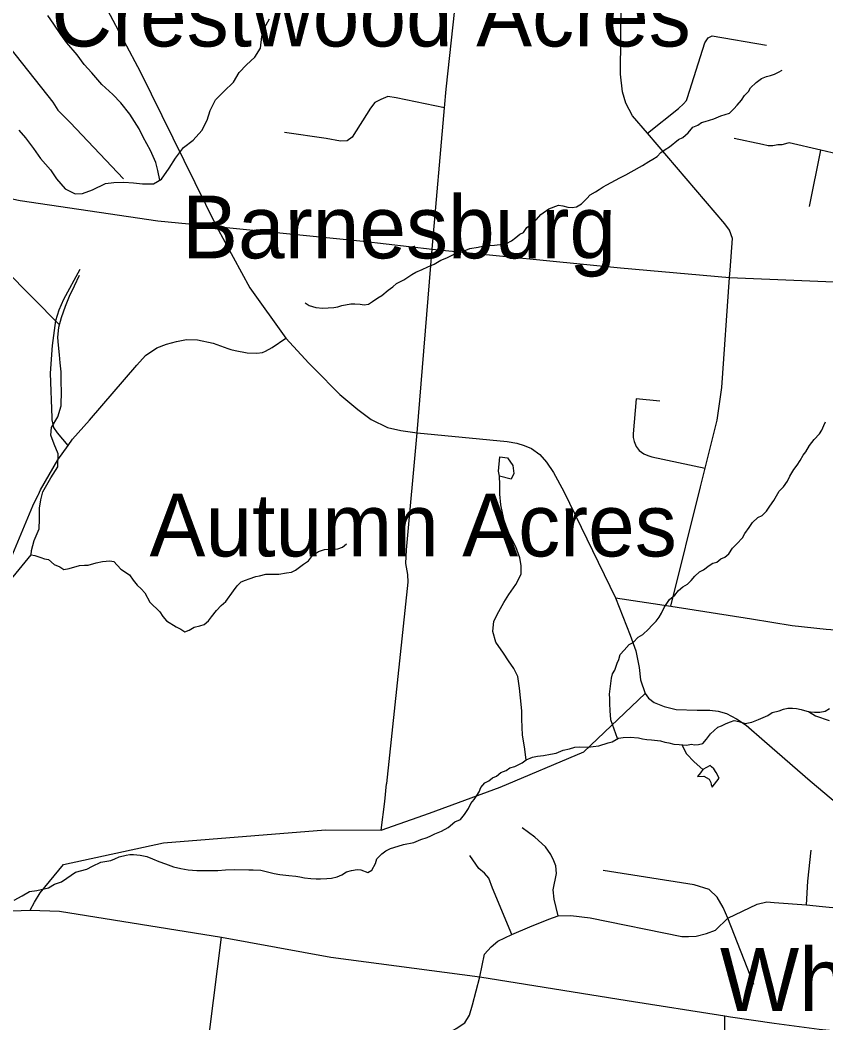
# Model space of a CAD drawing. Extents: x 0 to 34, y 0 to 22.
# Drawn here: x 2.395 to 3.408, y 15.023 to 16.285 of the extents above; entities that cross this region are included whole.
import ezdxf

# ---------------------------------------------------------------- set-up
doc = ezdxf.new("R2010")
doc.units = 0
for name, color, linetype in [('GM_X_County_Road', 7, 'Continuous'), ('GM_X_County_ROW', 7, 'Continuous'), ('GM_X_Minor_Lake', 7, 'Continuous'), ('GM_X_Minor_River', 7, 'Continuous'), ('GM_X_Township_Subdivision', 7, 'Continuous'), ('GM_X_Unincorporated_Text', 7, 'Continuous')]:
    doc.layers.add(name, color=color, linetype=linetype)

msp = doc.modelspace()

# ---------------------------------------------------------------- linework, layer by layer
at = {"layer": 'GM_X_County_Road'}
for points in [[(2.8559, 15.3242), (2.8828, 15.5776), (2.8823, 15.5871), (2.88, 15.6009), (2.8808, 15.6183), (2.8941, 15.7652), (2.913, 15.9963), (2.9286, 16.1743), (2.9306, 16.1979), (2.9499, 16.3756), (2.9714, 16.57), (2.9729, 16.5972), (2.9738, 16.6003), (2.9747, 16.6018), (2.978, 16.6059), (2.9836, 16.6083), (3.0077, 16.6072)], [(3.2878, 15.9702), (3.2906, 16.01), (3.287, 16.0204), (3.2811, 16.0285), (3.1838, 16.1424), (3.1651, 16.1641), (3.1565, 16.1802), (3.1523, 16.1945), (3.1498, 16.2167), (3.1509, 16.3102), (3.153, 16.3194), (3.1554, 16.3229), (3.1594, 16.3234), (3.1901, 16.3171), (3.1974, 16.3189), (3.2011, 16.3245), (3.2039, 16.3381), (3.2263, 16.5685)], [(2.2074, 16.5345), (2.2273, 16.5312), (2.2755, 16.511), (2.3238, 16.4892), (2.3831, 16.4487), (2.4345, 16.4035), (2.4589, 16.3735), (2.484, 16.336), (2.5458, 16.2199), (2.6419, 16.0249), (2.6836, 15.948), (2.7291, 15.8843), (2.758, 15.8531), (2.7648, 15.8462)], [(2.208, 16.349), (2.2477, 16.3455), (2.274, 16.3389), (2.2886, 16.332), (2.3179, 16.3136), (2.3818, 16.2496), (2.4358, 16.1813), (2.4424, 16.1714), (2.4579, 16.1557), (2.5248, 16.0849)], [(2.0624, 16.1544), (2.0789, 16.1495), (2.3218, 16.0727), (2.3948, 16.0576), (2.5679, 16.0322), (2.6419, 16.0249), (2.8264, 16.0064), (2.913, 15.9963), (3.15, 15.9729), (3.2871, 15.9607), (3.469, 15.9531), (3.6377, 15.9467), (3.7269, 15.9403), (3.8777, 15.9247), (3.9714, 15.9095), (4.1621, 15.8689), (4.3548, 15.8285)], [(2.4351, 15.7841), (2.4329, 15.8403), (2.4357, 15.8752), (2.4399, 15.9066), (2.444, 15.9202), (2.4497, 15.9337), (2.4704, 15.9712)], [(3.2132, 15.5475), (3.2504, 15.6976), (3.2563, 15.7208), (3.2715, 15.7814), (3.2775, 15.8223), (3.2871, 15.9607), (3.2878, 15.9702), (3.2878, 15.9702)], [(2.4175, 15.6875), (2.4178, 15.6879), (2.4205, 15.6936), (2.4423, 15.7314), (2.4552, 15.7496), (2.4608, 15.7576), (2.4819, 15.7813), (2.5417, 15.8505), (2.5526, 15.8628), (2.5669, 15.8723), (2.5788, 15.8769), (2.5914, 15.8804), (2.604, 15.8828), (2.618, 15.8824), (2.6376, 15.8781), (2.6561, 15.8713), (2.6599, 15.8703), (2.6655, 15.8691), (2.6802, 15.8661), (2.6925, 15.8656), (2.6998, 15.8665), (2.7035, 15.868), (2.7119, 15.8726), (2.7291, 15.8843)], [(2.7648, 15.8462), (2.7968, 15.8135), (2.8196, 15.7946), (2.8362, 15.7823), (2.8568, 15.7721), (2.8737, 15.7683), (2.8941, 15.7652), (3.0075, 15.7545), (3.0197, 15.7525), (3.0289, 15.7494), (3.0381, 15.7458), (3.0483, 15.7382), (3.057, 15.7285), (3.0657, 15.7154), (3.0785, 15.6914), (3.1437, 15.5578), (3.162, 15.5109), (3.1691, 15.491), (3.1734, 15.4703), (3.1752, 15.4547), (3.1808, 15.4374), (3.185, 15.4317), (3.1922, 15.4263), (3.2048, 15.421), (3.2199, 15.4175), (3.2464, 15.4165), (3.2622, 15.4165), (3.2728, 15.4154), (3.2832, 15.4124), (3.2958, 15.4054), (3.3078, 15.3978), (3.331, 15.3776), (3.3884, 15.3276), (3.4866, 15.245)], [(2.4552, 15.7496), (2.4417, 15.7656), (2.4373, 15.7722), (2.4352, 15.7818), (2.4352, 15.7838), (2.4351, 15.7841)], [(2.2258, 15.2235), (2.2523, 15.2469), (2.2626, 15.258), (2.2702, 15.2722), (2.2781, 15.2876), (2.2823, 15.3117), (2.2837, 15.3313), (2.289, 15.3499), (2.3002, 15.3794), (2.3158, 15.4331), (2.3396, 15.5024), (2.3499, 15.5283), (2.3567, 15.552), (2.3636, 15.5654), (2.3774, 15.5931), (2.4109, 15.6737), (2.4175, 15.6875)], [(3.1437, 15.5578), (3.2132, 15.5475), (3.3147, 15.5315), (3.3657, 15.5231), (3.4084, 15.5185), (3.4388, 15.5162), (3.6274, 15.5008)], [(2.2258, 15.2235), (2.2987, 15.186), (2.3184, 15.1766), (2.3423, 15.1693), (2.373, 15.1638), (2.4076, 15.1648), (2.4442, 15.1636), (2.6483, 15.131), (2.7856, 15.1056), (2.9731, 15.0809), (3.1585, 15.0511), (3.281, 15.0319), (3.2884, 15.0308), (3.343, 15.0226), (3.3998, 15.0151), (3.5922, 14.9963), (3.5999, 14.9956)], [(2.4076, 15.1648), (2.4128, 15.1748), (2.4199, 15.1866), (2.4496, 15.2222)], [(2.6198, 14.8825), (2.6281, 14.9717), (2.6483, 15.131)]]:
    msp.add_lwpolyline(points, dxfattribs=at)
at = {"layer": 'GM_X_County_ROW'}
for points in [[(2.4496, 15.2222), (2.5753, 15.2496), (2.6899, 15.2589), (2.7788, 15.2659), (2.8491, 15.2655), (2.9098, 15.287), (2.9987, 15.3197), (3.104, 15.3642), (3.1808, 15.4374)], [(2.8491, 15.2655), (2.8535, 15.3015), (2.8558, 15.3238), (2.8559, 15.3242)]]:
    msp.add_lwpolyline(points, dxfattribs=at)
at = {"layer": 'GM_X_Minor_Lake'}
for points in [[(2.9979, 15.7108), (2.9965, 15.7173), (2.998, 15.7352), (3.0079, 15.7338), (3.0145, 15.7242), (3.0158, 15.7143), (3.0126, 15.7071)], [(3.0126, 15.7071), (2.9979, 15.7108)], [(3.2534, 15.3417), (3.2505, 15.3376), (3.2466, 15.3331), (3.2546, 15.3333), (3.2613, 15.3297), (3.2635, 15.3255), (3.2638, 15.3228), (3.2653, 15.3198), (3.2739, 15.331), (3.2702, 15.3379), (3.2673, 15.3425), (3.2643, 15.3452), (3.2628, 15.3468)], [(3.2628, 15.3468), (3.2534, 15.3417)]]:
    msp.add_lwpolyline(points, dxfattribs=at)
at = {"layer": 'GM_X_Minor_River'}
msp.add_line((2.3754, 15.9707), (2.4443, 15.9014), dxfattribs=at)
for points in [[(2.5705, 16.0832), (2.568, 16.0956), (2.5656, 16.1055), (2.5587, 16.1205), (2.5496, 16.1375), (2.5446, 16.1479), (2.5328, 16.1664), (2.5214, 16.1804), (2.5114, 16.1909), (2.4977, 16.2038), (2.4851, 16.2182), (2.4755, 16.2287), (2.4666, 16.241), (2.4537, 16.2562), (2.446, 16.2667), (2.4372, 16.2794), (2.4295, 16.2903)], [(2.3933, 16.1462), (2.4018, 16.1365), (2.4117, 16.123), (2.4205, 16.1106), (2.4331, 16.0962), (2.4404, 16.085), (2.4515, 16.0722), (2.4639, 16.0662), (2.4734, 16.0667), (2.4857, 16.0713), (2.5022, 16.0789), (2.5125, 16.0802), (2.5251, 16.0806), (2.5376, 16.08), (2.5489, 16.0785), (2.5626, 16.0786), (2.5727, 16.0844), (2.5821, 16.0983), (2.5904, 16.111), (2.6002, 16.1244), (2.6126, 16.1337), (2.6232, 16.1456), (2.6299, 16.1587), (2.634, 16.1708), (2.6404, 16.1843), (2.651, 16.1947), (2.663, 16.2066), (2.6705, 16.2186), (2.6795, 16.2282), (2.69, 16.2379), (2.6971, 16.2495), (2.699, 16.2639), (2.7023, 16.2748), (2.7083, 16.2861)], [(2.7533, 15.929), (2.7582, 15.9258), (2.7668, 15.9229), (2.7756, 15.9223), (2.7824, 15.9225), (2.7893, 15.9231), (2.7946, 15.9241), (2.7996, 15.9255), (2.8107, 15.9278), (2.816, 15.9277), (2.8225, 15.9271), (2.8274, 15.9266), (2.8331, 15.9272), (2.8382, 15.9305), (2.8447, 15.9352), (2.8498, 15.9381), (2.8579, 15.9451), (2.8638, 15.9492), (2.8684, 15.9532), (2.8773, 15.9579), (2.8874, 15.9645), (2.8924, 15.9674), (2.9005, 15.971), (2.9078, 15.9742), (2.9155, 15.9774), (2.924, 15.9825), (2.9317, 15.9857), (2.9398, 15.9897), (2.9482, 15.9921), (2.9605, 15.9975), (2.9708, 15.9991), (2.98, 16.0011), (2.9914, 16.0016), (3.0021, 16.0028), (3.0067, 16.0038), (3.0129, 16.0071), (3.0183, 16.0111), (3.0234, 16.0152), (3.028, 16.0173), (3.032, 16.0237), (3.0413, 16.0303), (3.0499, 16.0399), (3.06, 16.0473), (3.0719, 16.0519), (3.0776, 16.051), (3.0836, 16.0493), (3.0893, 16.0487), (3.0947, 16.0497), (3.1008, 16.0534), (3.1075, 16.0604), (3.1118, 16.0649), (3.1184, 16.0685), (3.123, 16.0714), (3.128, 16.0751), (3.1327, 16.0776), (3.1489, 16.0863), (3.1566, 16.0899), (3.1635, 16.0939), (3.1778, 16.1019), (3.1856, 16.1066), (3.1906, 16.1099), (3.196, 16.1132), (3.2007, 16.118), (3.2061, 16.122), (3.2116, 16.1253), (3.2228, 16.1345), (3.2282, 16.137), (3.2349, 16.1429), (3.2411, 16.15), (3.2473, 16.1525), (3.2519, 16.1558), (3.2565, 16.1572), (3.2673, 16.1603), (3.2761, 16.1642), (3.2815, 16.166), (3.2869, 16.1677), (3.2923, 16.1729), (3.2966, 16.1777), (3.3021, 16.1841), (3.3061, 16.1897), (3.3108, 16.1949), (3.3136, 16.1994), (3.3206, 16.206), (3.3272, 16.2112), (3.3337, 16.2136), (3.3387, 16.215), (3.3437, 16.2168), (3.3487, 16.2193), (3.3534, 16.2215)], [(2.4089, 15.6119), (2.4093, 15.6172), (2.4126, 15.63), (2.4187, 15.6447), (2.4194, 15.6569), (2.4193, 15.6706), (2.4207, 15.6812), (2.4236, 15.691), (2.4335, 15.7086), (2.4422, 15.7225), (2.4426, 15.7388), (2.4376, 15.7511), (2.4333, 15.7623), (2.4343, 15.7721), (2.4422, 15.7856), (2.4464, 15.7992), (2.4468, 15.8182), (2.4463, 15.8285), (2.4463, 15.8422), (2.4454, 15.8536), (2.4445, 15.8635), (2.4429, 15.8757), (2.4424, 15.8853), (2.4435, 15.8985), (2.4468, 15.9103), (2.4517, 15.9246), (2.457, 15.9374), (2.4634, 15.9505), (2.4694, 15.9637)], [(3.1463, 15.3807), (3.1376, 15.4042), (3.1374, 15.4107), (3.1371, 15.4152), (3.1367, 15.4252), (3.1364, 15.4313), (3.1362, 15.4366), (3.1368, 15.4434), (3.1377, 15.4499), (3.1387, 15.4567), (3.1399, 15.4624), (3.1427, 15.4669), (3.1456, 15.4756), (3.1477, 15.4801), (3.1497, 15.4865), (3.1544, 15.4921), (3.1607, 15.4991), (3.1657, 15.5017), (3.172, 15.5083), (3.1782, 15.5116), (3.1852, 15.5186), (3.1895, 15.5231), (3.1946, 15.5283), (3.1985, 15.5335), (3.2013, 15.5384), (3.2049, 15.5455), (3.2117, 15.5556), (3.2183, 15.5611), (3.223, 15.5671), (3.2285, 15.5715), (3.2343, 15.5748), (3.239, 15.5796), (3.2433, 15.5852), (3.2491, 15.5907), (3.2542, 15.5932), (3.2615, 15.5984), (3.2662, 15.6013), (3.2711, 15.6027), (3.2762, 15.6067), (3.2812, 15.6089), (3.2863, 15.6133), (3.2906, 15.6204), (3.2961, 15.6256), (3.3032, 15.6334), (3.3063, 15.6386), (3.3119, 15.6465), (3.3159, 15.6524), (3.3225, 15.6587), (3.3283, 15.6616), (3.3337, 15.6668), (3.3377, 15.6732), (3.3428, 15.6803), (3.3496, 15.6919), (3.3551, 15.6974), (3.3599, 15.7045), (3.3631, 15.7109), (3.3679, 15.7192), (3.3722, 15.7247), (3.3758, 15.7304), (3.3798, 15.7371), (3.3829, 15.7416), (3.3877, 15.7495), (3.3936, 15.7569), (3.4003, 15.7643), (3.4031, 15.7688), (3.4055, 15.7745), (3.4079, 15.7794)], [(3.0313, 15.3539), (3.0291, 15.3704), (3.0268, 15.3849), (3.0263, 15.3952), (3.0258, 15.4051), (3.0257, 15.4158), (3.0242, 15.4322), (3.0229, 15.444), (3.021, 15.4589), (3.0156, 15.4689), (3.009, 15.4785), (3.0027, 15.4882), (2.9932, 15.5021), (2.9893, 15.5155), (2.9908, 15.5284), (2.9968, 15.5408), (3.0031, 15.5521), (3.0095, 15.5618), (3.0185, 15.5745), (3.0249, 15.5877), (3.0252, 15.5987), (3.0235, 15.6083), (3.0182, 15.6221), (3.0091, 15.6394), (3.0038, 15.6551), (3.0017, 15.6647), (2.9993, 15.6747), (2.9981, 15.6884), (2.998, 15.7005), (2.9979, 15.7108)], [(2.4089, 15.6119), (2.4134, 15.611), (2.421, 15.6085), (2.4255, 15.6069), (2.4304, 15.606), (2.4375, 15.5997), (2.4446, 15.5968), (2.4499, 15.5936), (2.4567, 15.5946), (2.4694, 15.5984), (2.4759, 15.599), (2.4804, 15.5989), (2.4904, 15.602), (2.4984, 15.6037), (2.5076, 15.6042), (2.5129, 15.6037), (2.5214, 15.5939), (2.5322, 15.5868), (2.537, 15.5802), (2.5421, 15.5739), (2.5469, 15.5692), (2.5517, 15.5641), (2.5579, 15.5525), (2.5705, 15.5404), (2.5745, 15.5342), (2.5789, 15.5287), (2.5913, 15.5215), (2.5969, 15.5183), (2.6021, 15.5151), (2.6075, 15.5173), (2.6137, 15.5209), (2.621, 15.5226), (2.6263, 15.5243), (2.6318, 15.5288), (2.6357, 15.534), (2.642, 15.5418), (2.6475, 15.5481), (2.6537, 15.5533), (2.6632, 15.5667), (2.668, 15.5731), (2.673, 15.5779), (2.6784, 15.58), (2.683, 15.5818), (2.6911, 15.5846), (2.6957, 15.5856), (2.7037, 15.5877), (2.7094, 15.5875), (2.7201, 15.5876), (2.73, 15.5892), (2.7361, 15.5902), (2.7411, 15.5927), (2.7512, 15.6001), (2.7574, 15.6045), (2.7626, 15.6112), (2.7699, 15.6163), (2.7776, 15.6187), (2.786, 15.6189), (2.7943, 15.6194), (2.8001, 15.6215), (2.8052, 15.6256)], [(2.363, 15.5565), (2.4089, 15.6119)], [(3.0979, 15.3703), (3.1093, 15.3699), (3.1154, 15.3709), (3.1226, 15.3715), (3.1345, 15.3753), (3.1395, 15.3767), (3.1476, 15.3814), (3.1534, 15.382), (3.1621, 15.3826), (3.1727, 15.3815), (3.1777, 15.3806), (3.183, 15.3797), (3.189, 15.3791), (3.2004, 15.3781), (3.2057, 15.3764), (3.2106, 15.3755), (3.217, 15.3738), (3.2239, 15.3732), (3.2333, 15.3726), (3.2387, 15.3736), (3.2436, 15.373), (3.2482, 15.3733), (3.2536, 15.3747), (3.2579, 15.3799), (3.263, 15.3866), (3.2724, 15.3951), (3.277, 15.3969), (3.2828, 15.3998), (3.2881, 15.4019), (3.2931, 15.4033), (3.2988, 15.4024), (3.3067, 15.3995), (3.3151, 15.4015), (3.3236, 15.4047), (3.3351, 15.4097), (3.3409, 15.4134), (3.3494, 15.4158), (3.3551, 15.4179), (3.3605, 15.4189), (3.3662, 15.4191), (3.3715, 15.4186), (3.3772, 15.4173), (3.3843, 15.4152), (3.3889, 15.4143), (3.3938, 15.4138), (3.4007, 15.414), (3.4075, 15.4153), (3.4126, 15.4186)], [(3.3865, 15.4148), (3.3953, 15.4094), (3.4122, 15.4033)], [(2.3872, 15.1773), (2.3976, 15.1827), (2.4065, 15.1885), (2.4157, 15.1898), (2.4306, 15.1928), (2.438, 15.1975), (2.4468, 15.2007), (2.4534, 15.2051), (2.4646, 15.2128), (2.4788, 15.2166), (2.4857, 15.2202), (2.4965, 15.2252), (2.5091, 15.2275), (2.5138, 15.2293), (2.5195, 15.2318), (2.5283, 15.2339), (2.5329, 15.2349), (2.5375, 15.2351), (2.5458, 15.2341), (2.5541, 15.2324), (2.5613, 15.2295), (2.5692, 15.2262), (2.5775, 15.223), (2.5876, 15.2193), (2.5971, 15.2171), (2.6062, 15.2157), (2.6172, 15.2146), (2.6252, 15.2148), (2.6331, 15.2146), (2.6434, 15.2147), (2.6533, 15.2155), (2.6647, 15.216), (2.6826, 15.2158), (2.6879, 15.2157), (2.6974, 15.215), (2.7027, 15.2141), (2.7095, 15.2124), (2.7144, 15.2108), (2.7216, 15.2098), (2.7326, 15.2084), (2.7417, 15.2077), (2.7466, 15.2068), (2.7527, 15.2055), (2.7603, 15.2049), (2.7671, 15.2043), (2.7728, 15.2042), (2.7804, 15.2047), (2.7865, 15.2053), (2.7934, 15.2067), (2.7996, 15.2095), (2.8054, 15.2132), (2.8115, 15.2149), (2.8188, 15.2162), (2.8233, 15.2157), (2.832, 15.2124), (2.837, 15.215), (2.8418, 15.2236), (2.8435, 15.2296), (2.8497, 15.2359), (2.8548, 15.2396), (2.8606, 15.2425), (2.8705, 15.2452), (2.877, 15.2473), (2.89, 15.25), (2.8989, 15.2536), (2.9066, 15.2564), (2.9116, 15.2582), (2.9166, 15.2611), (2.9247, 15.2643), (2.9331, 15.269), (2.9417, 15.276), (2.9486, 15.2789), (2.9537, 15.2852), (2.9589, 15.2927), (2.9617, 15.2991), (2.966, 15.3043), (2.9692, 15.3091), (2.972, 15.3136), (2.9744, 15.3193), (2.9795, 15.3252), (2.9842, 15.3277), (2.9888, 15.3314), (2.9938, 15.3336), (2.9993, 15.338), (3.0062, 15.3405), (3.0109, 15.3438), (3.017, 15.3455), (3.0262, 15.3502), (3.0313, 15.3539), (3.0394, 15.3574), (3.0455, 15.3588), (3.0531, 15.3593), (3.0619, 15.361), (3.0692, 15.3623), (3.078, 15.3663), (3.0857, 15.3679), (3.0926, 15.37), (3.0979, 15.3703)], [(3.227, 15.373), (3.233, 15.3616), (3.2426, 15.3515), (3.2534, 15.3417)]]:
    msp.add_lwpolyline(points, dxfattribs=at)
at = {"layer": 'GM_X_Township_Subdivision'}
for points in [[(3.1838, 16.1424), (3.2227, 16.1736), (3.2292, 16.1794), (3.2328, 16.1837), (3.2344, 16.1873), (3.256, 16.2561), (3.26, 16.2623), (3.2651, 16.2648), (3.3336, 16.2531)], [(2.9286, 16.1743), (2.8679, 16.1868), (2.8575, 16.1884), (2.8487, 16.1847), (2.841, 16.1811), (2.8354, 16.1738), (2.8126, 16.1372), (2.8063, 16.1328), (2.7977, 16.1325), (2.7798, 16.1359), (2.7273, 16.1432)], [(3.3606, 16.1298), (3.3527, 16.1277), (3.35, 16.1278), (3.3477, 16.1276), (3.3458, 16.1272), (3.3437, 16.1267), (3.3415, 16.1265), (3.3401, 16.1263), (3.3379, 16.1264), (3.3355, 16.1266), (3.3287, 16.1281), (3.2927, 16.1358)], [(3.4871, 16.0822), (3.4822, 16.0885), (3.4734, 16.0966), (3.4629, 16.1028), (3.4476, 16.1091), (3.4233, 16.1159), (3.4019, 16.1209), (3.362, 16.1302), (3.3606, 16.1298)], [(3.3876, 16.0501), (3.4019, 16.1209)], [(3.1996, 15.8051), (3.1695, 15.8083), (3.1657, 15.7643), (3.1657, 15.7596), (3.167, 15.7544), (3.1697, 15.7484), (3.1735, 15.7432), (3.1792, 15.7388), (3.1844, 15.7367), (3.1893, 15.735), (3.2563, 15.7208)], [(3.0714, 15.1579), (3.0665, 15.1788), (3.0654, 15.1903), (3.0693, 15.2111), (3.0686, 15.2207), (3.066, 15.2271), (3.0625, 15.2349), (3.0558, 15.2444), (3.0424, 15.2569), (3.0264, 15.2683)], [(3.3433, 15.1746), (3.3838, 15.1717), (3.4039, 15.1695), (3.4508, 15.1648), (3.4566, 15.1692), (3.4581, 15.201), (3.4585, 15.2052), (3.4596, 15.2095), (3.4615, 15.2137), (3.4636, 15.2171), (3.4866, 15.245)], [(3.0132, 15.1342), (2.989, 15.1927), (2.9842, 15.205), (2.9788, 15.2114), (2.9719, 15.2173), (2.9603, 15.2338)], [(3.3838, 15.1717), (3.3857, 15.2012), (3.3898, 15.2404)], [(3.3178, 15.0715), (3.285, 15.1546), (3.279, 15.1684), (3.2715, 15.1811), (3.2616, 15.1907), (3.2426, 15.1968), (3.1283, 15.2148)], [(2.9731, 15.0809), (2.979, 15.1096), (2.9871, 15.1187), (2.9958, 15.1258), (3.0132, 15.1342), (3.036, 15.1439), (3.0596, 15.1535), (3.0714, 15.1579), (3.0873, 15.1582), (3.1116, 15.1551), (3.2271, 15.1318), (3.2355, 15.1316), (3.245, 15.1322), (3.258, 15.1353), (3.2694, 15.1399), (3.285, 15.1546), (3.322, 15.1725), (3.3338, 15.1753), (3.3433, 15.1746)], [(2.8788, 14.8884), (2.903, 14.9595), (2.906, 14.9705), (2.9086, 14.9773), (2.9106, 14.9824), (2.9175, 14.9927), (2.9243, 15.0038), (2.9323, 15.0098), (2.9433, 15.0159), (2.9542, 15.0232), (2.96, 15.0328), (2.9638, 15.0458), (2.9731, 15.0809)], [(3.1791, 14.9817), (3.1891, 14.9662), (3.2089, 14.9569), (3.2321, 14.9514), (3.2569, 14.9574), (3.2696, 14.9635), (3.2812, 14.9844), (3.2812, 15.0159), (3.281, 15.0319)]]:
    msp.add_lwpolyline(points, dxfattribs=at)

# ---------------------------------------------------------------- texts
at = {"layer": 'GM_X_Unincorporated_Text'}
for s, height, p in [('Crestwood Acres', 0.078977, (2.4342, 16.2515)), ('Barnesburg', 0.07898, (2.5984, 15.9849)), ('Autumn Acres', 0.078977, (2.5575, 15.6099)), ('White Oak', 0.07898, (3.275, 15.0382))]:
    msp.add_text(s, height=height, rotation=0, dxfattribs=at).set_placement(p)

doc.saveas('drawing.dxf')
